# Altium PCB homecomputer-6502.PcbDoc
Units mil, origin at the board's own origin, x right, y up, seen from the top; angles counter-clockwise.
Board outline 6299.21 x 3937.01 mil, 2 copper layers (Top, Bottom), stack 61.811 mil thick; 48 components, 83 nets, 386 pads, 147 vias.
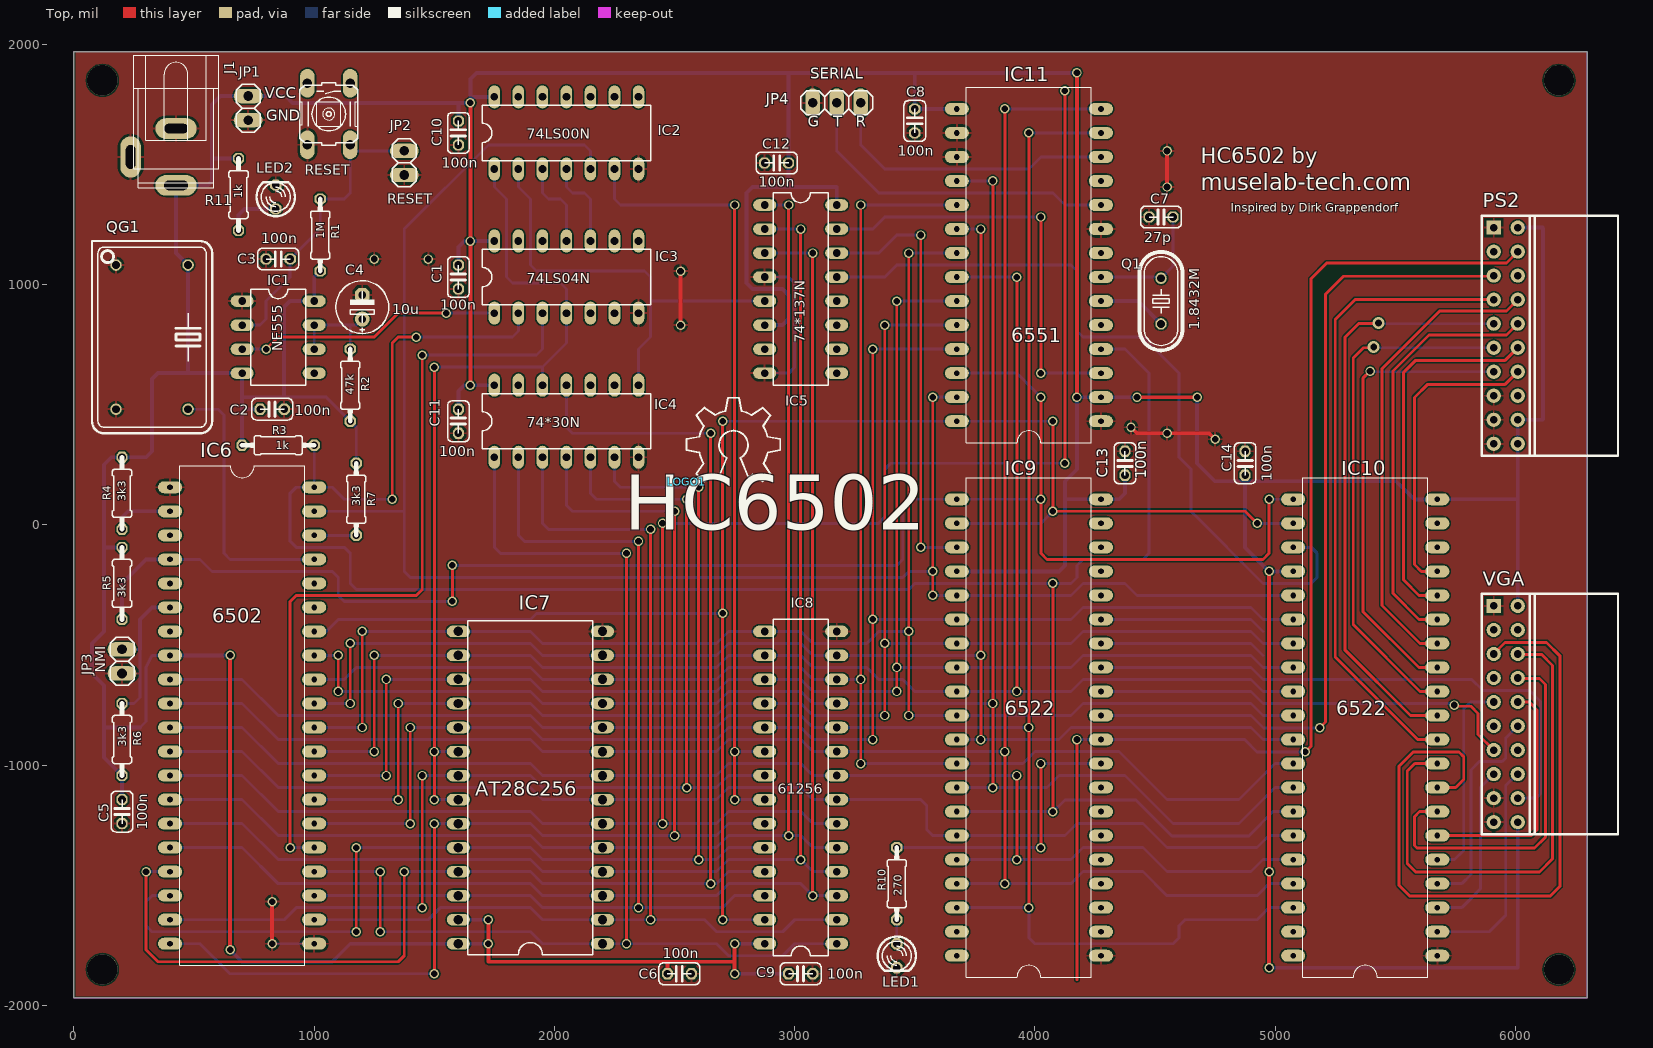
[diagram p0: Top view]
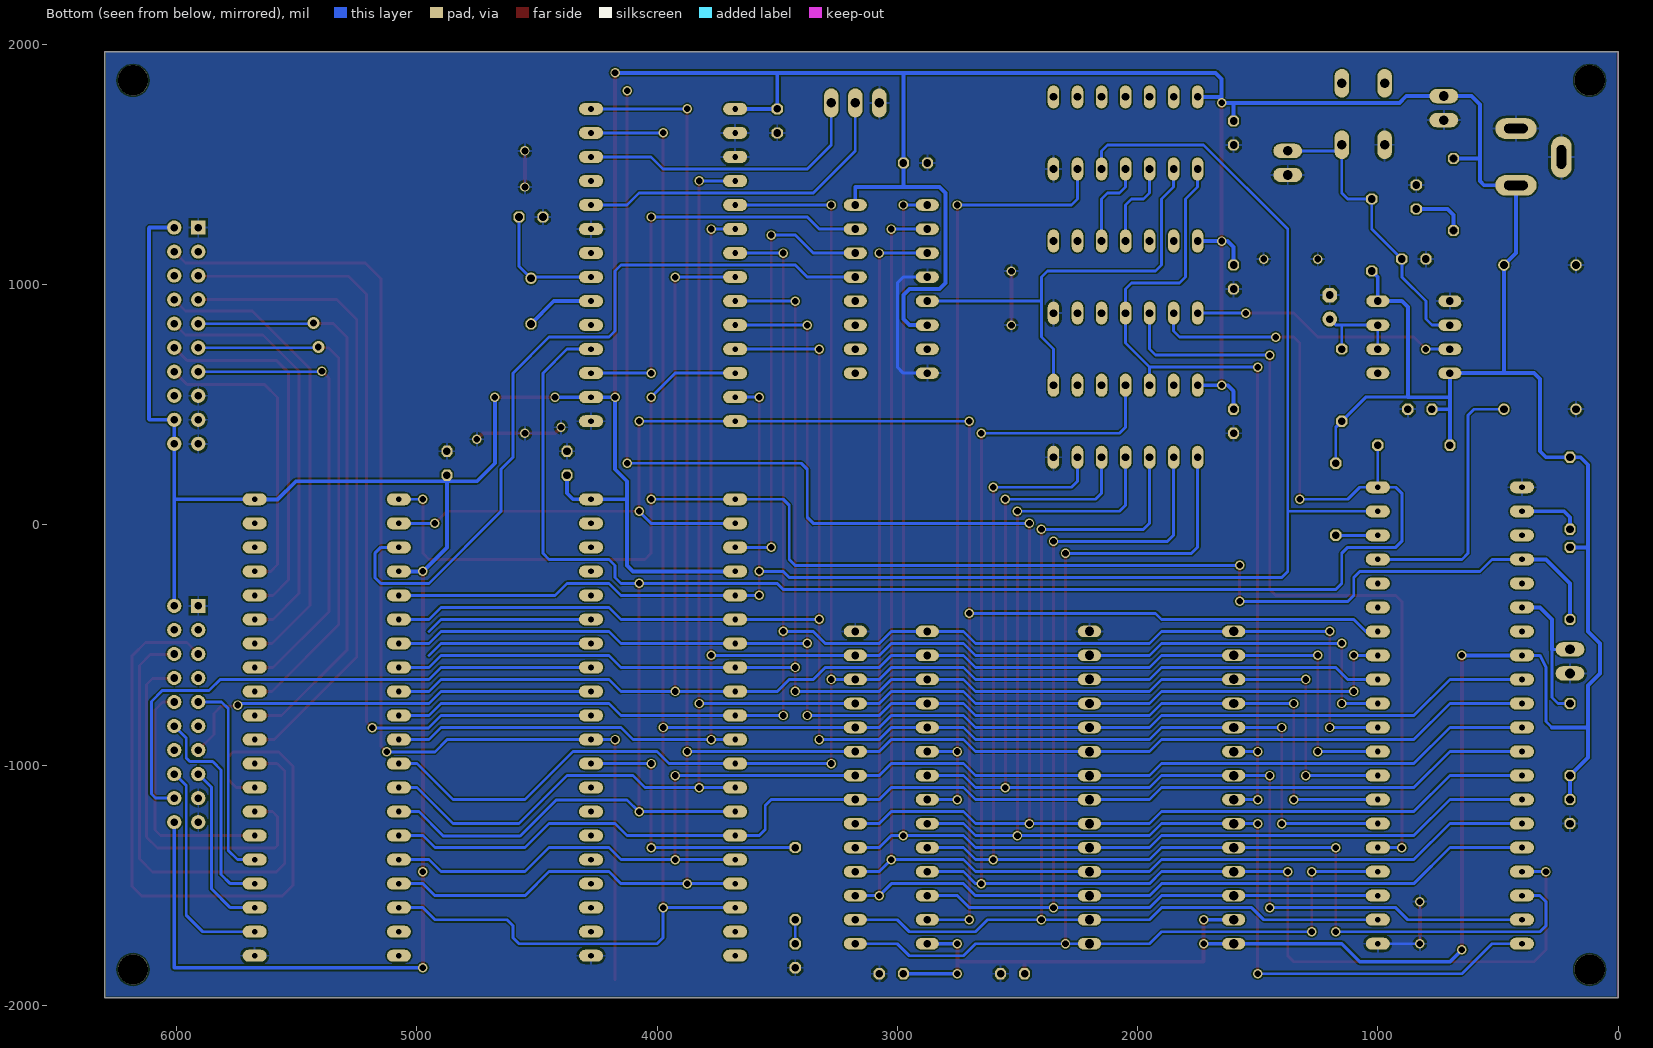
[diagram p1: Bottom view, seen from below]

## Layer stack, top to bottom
Top Solder: solder mask 0.4, Solder Resist, Dk 3.5
Top: signal copper 1.378
Dielectric 1: core 59.0551, FR-4, Dk 4.8
Bottom: signal copper 1.378
Bottom Solder: solder mask 0.4, Solder Resist, Dk 3.5

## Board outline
0,-1968.51 6299.21,-1968.51 6299.21,1968.51 0,1968.51

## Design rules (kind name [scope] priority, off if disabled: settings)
Clearance [All] p1: gap=5.91 ignorepadtopadclearanceinfootprint=FALSE except(0: SMDPad-SMDPad SMDPad-THPad SMDPad-Via)
Clearance "Clearance (Same Net)" [All] p2: gap=0 ignorepadtopadclearanceinfootprint=FALSE except(5.91: SMDPad-SMDPad SMDPad-THPad SMDPad-Via)
HoleSize HoleSize_1 [All] p1: absolutevalues=TRUE maxlimit=100000 minlimit=11.81 maxpercent=80.000 minpercent=20.000
HoleSize [All] p2: absolutevalues=TRUE maxlimit=100 minlimit=1 maxpercent=80.000 minpercent=20.000
HoleToHoleClearance mdViaViaSameLayer [All] p1: gap=19.68 allowstackedmicrovias=TRUE
HoleToHoleClearance [All] p2: gap=10 allowstackedmicrovias=TRUE
PasteMaskExpansion mlMinCreamFrame [All] p1: expansion=0
PasteMaskExpansion [All] p2: expansion=0
PolygonConnect PolygonConnect_1 [All] p1: connectstyle=Relief reliefconductorwidth=10 reliefentries=4 polygonreliefangle="90 Angle" airgapwidth=10
PolygonConnect [All] p2: connectstyle=Relief reliefconductorwidth=10 reliefentries=4 polygonreliefangle="90 Angle" airgapwidth=10
RoutingVias [All] p1: holewidth=28 width=50 viastyle="Through Hole" minholewidth=28 minwidth=50 maxholewidth=28 maxwidth=50
SilkToSilkClearance [All] p1 off: silktosilkclearance=10
SilkToSolderMaskClearance [IsPad] p1 off: minsilkscreentomaskgap=10 clearancetoexposedcopper=TRUE
SolderMaskExpansion mlMinStopFrame [All] p1: expansion=2.95
SolderMaskExpansion [All] p2: expansion=4
Width Width_1 [All] p1: maxlimit=100000 minlimit=5.91 preferedwidth=10
Width [All] p2: maxlimit=10 minlimit=10 preferedwidth=10
25 further rules are at their usual default settings.

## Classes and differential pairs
component class homecomputer-6502_5: J2 muselab-tech.com PS2 VGA
component class homecomputer-6502_0: C1 C2 C3 C4 C5 C8 C9 C10 C11 C12 C13 C14 IC1 IC3 J1 JP1 JP2 LED2 LOGO1 QG1 R1 R2 R3 R11 RESET
component class homecomputer-6502_1: IC2 IC4 IC5
component class homecomputer-6502_2: C6 IC6 IC7 IC8 JP3 R4 R5 R6 R7
component class homecomputer-6502_3: IC9 IC10 LED1 R10
component class homecomputer-6502_4: C7 IC11 JP4 Q1
net class A[0..15]: A0 A1 A2 A3 A4 A5 A6 A7 A8 A9 A10 A11 A12 A13 A14 A15
net class D[0..7]: D0 D1 D2 D3 D4 D5 D6 D7

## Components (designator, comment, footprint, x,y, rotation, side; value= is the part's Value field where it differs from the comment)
C1 "100n" C025-024X044 1600,1031.49 r90 top
C2 "100n" C025-024X044 825,481.49 r180 top
C3 "100n" C025-024X044 850,1106.49 r0 top
C4 "10u" E2,5-6E 1200,906.49 r90 top
C5 "100n" C025-024X044 200,-1193.51 r90 top
C6 "100n" C025-024X044 2520,-1868.51 r180 top
C7 "27p" C025-024X044 4525,1281.49 r0 top
C8 "100n" C025-024X044 3500,1681.49 r90 top
C9 "100n" C025-024X044 3025,-1868.51 r180 top
C10 "100n" C025-024X044 1600,1631.49 r90 top
C11 "100n" C025-024X044 1600,431.49 r90 top
C12 "100n" C025-024X044 2925,1506.49 r0 top
C13 "100n" C025-024X044 4375,256.49 r270 top
C14 "100n" C025-024X044 4875,256.49 r270 top
IC1 "NE555" DIL-08 850,781.49 r270 top
IC2 "74LS00N" DIL14 2050,1631.49 r0 top
IC3 "74LS04N" DIL14 2050,1031.49 r0 top
IC4 "74*30N" DIL14 2050,431.49 r0 top
IC5 "74*137N" DIL16 3025,981.49 r270 top
IC6 "6502" DIP40 700,-793.51 r270 top
IC7 "AT28C256" DIL28-6 1900,-1093.51 r90 top
IC8 "61256" DIL28-3 3025,-1093.51 r90 top
IC9 "6522" DIP40 3975,-843.51 r90 top
IC10 "6522" DIP40 5375,-843.51 r90 top locked
IC11 "6551" DIP28 3975,1081.49 r90 top
J1 "POWER1" SPC4078 425,1531.49 r270 top
JP1 "POWER2" 1X02 725,1735 r270 top
JP2 "RESET" 1X02 1375,1506.49 r270 top
JP3 "NMI" 1X02 200,-568.51 r270 top
JP4 "SERIAL" 1X03 3175,1756.49 r0 top
LED1 "LED3MM" LED3MM 3425,-1793.51 r270 top
LED2 "LED3MM" LED3MM 840,1365 r90 top
LOGO1 "OSHW_LOGO_8MILX0350-NT" OSHW_8X350_NOTEXT 2550,180 r0 top
muselab-tech.com "LOGO_MuseLab" LOGO_MUSELAB 5385,1495 r0 top
PS2 "IDC20" IDC20 5960,787.4 r270 top locked
Q1 "1.8432M" HC49U-V 4525,931.49 r90 top
QG1 "XO-14" DIL14S 325,781.49 r270 top
R1 "1M" 0204/7 1025,1206.49 r270 top
R2 "47k" 0204/7 1150,581.49 r270 top
R3 "1k" 0204/7 850,331.49 r180 top
R4 "3k3" 0204/7 200,131.49 r90 top
R5 "3k3" 0204/7 200,-243.51 r90 top
R6 "3k3" 0204/7 200,-893.51 r270 top
R7 "3k3" 0204/7 1175,106.49 r90 top
R10 "270" 0204/7 3425,-1493.51 r90 top
R11 "1k" 0204/7 685,1375 r90 top
RESET "10-XX" B3F-10XX 1060.63,1710.23 r270 top
VGA "IDC20" IDC20 5960,-787.4 r270 top locked

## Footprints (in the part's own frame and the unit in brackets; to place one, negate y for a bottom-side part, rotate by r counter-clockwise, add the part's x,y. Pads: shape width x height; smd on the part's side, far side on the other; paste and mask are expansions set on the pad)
1X02 [mil] "1X02"
  oval 60x120 hole 40: 1(-50,0) 2(50,0)
  silkscreen extent -100,-50 100,50
1X03 [mil] "1X03"
  oval 60x120 hole 40: 1(-100,0) 2(0,0) 3(100,0)
  silkscreen extent -150,-50 150,50
0204/7 [mil] "0204/7"
  oct 46.48x46.48 hole 32: 1(-150,0) 2(150,0)
  silkscreen extent -150,-40 150,40
B3F-10XX [mil] "B3F-10XX"
  oval 120x60 hole 40: 1(-128,89) 2(128,89) 3(-128,-89) 4(128,-89)
  silkscreen extent -130,-120 130,120
C025-024X044 [mil] "C025-024X044"
  oct 46.48x46.48 hole 32: 1(-50,0) 2(50,0)
  silkscreen extent -85,-45 85,45
DIL14 [mil] "DIL14"
  oval 48x96 hole 32: 1(-300,-150) 2(-200,-150) 3(-100,-150) 4(0,-150) 5(100,-150) 6(200,-150) 7(300,-150) 8(300,150) 9(200,150) 10(100,150) 11(0,150) 12(-100,150) 13(-200,150) 14(-300,150)
  silkscreen extent -350,-115 350,115
DIL14S [mil] "DIL14S"
  round 48 hole 32: 1(-300,-150) 7(300,-150) 8(300,150) 14(-300,150)
  silkscreen extent -400,-250 400,250
DIL16 [mil] "DIL16"
  oval 48x96 hole 32: 1(-350,-150) 2(-250,-150) 3(-150,-150) 4(-50,-150) 5(50,-150) 6(150,-150) 7(250,-150) 8(350,-150) 9(350,150) 10(250,150) 11(150,150) 12(50,150) 13(-50,150) 14(-150,150) 15(-250,150) 16(-350,150)
  silkscreen extent -400,-115 400,115
DIL28-3 [mil] "DIL28-3"
  oval 48x96 hole 32: 1(-650,-150) 2(-550,-150) 3(-450,-150) 4(-350,-150) 5(-250,-150) 6(-150,-150) 7(-50,-150) 8(50,-150) 9(150,-150) 10(250,-150) 11(350,-150) 12(450,-150) 13(550,-150) 14(650,-150) 15(650,150) 16(550,150) 17(450,150) 18(350,150) 19(250,150) 20(150,150) 21(50,150) 22(-50,150) 23(-150,150) 24(-250,150) 25(-350,150) 26(-450,150) 27(-550,150) 28(-650,150)
  silkscreen extent -700,-115 700,115
DIL28-6 [mil] "DIL28-6"
  oval 48x96 hole 39.37: 1(-650,-300) 2(-550,-300) 3(-450,-300) 4(-350,-300) 5(-250,-300) 6(-150,-300) 7(-50,-300) 8(50,-300) 9(150,-300) 10(250,-300) 11(350,-300) 12(450,-300) 13(550,-300) 14(650,-300) 15(650,300) 16(550,300) 17(450,300) 18(350,300) 19(250,300) 20(150,300) 21(50,300) 22(-50,300) 23(-150,300) 24(-250,300) 25(-350,300) 26(-450,300) 27(-550,300) 28(-650,300)
  silkscreen extent -695,-260 695,260
DIL-08 [mil] "DIL-08"
  oval 48x96 hole 32: 1(-150,-150) 2(-50,-150) 3(50,-150) 4(150,-150) 5(150,150) 6(50,150) 7(-50,150) 8(-150,150)
  silkscreen extent -200,-115 200,115
DIP28 [mil] "DIP28"
  oval 50x100 hole 24: 1(-650,-300) 2(-550,-300) 3(-450,-300) 4(-350,-300) 5(-250,-300) 6(-150,-300) 7(-50,-300) 8(50,-300) 9(150,-300) 10(250,-300) 11(350,-300) 12(450,-300) 13(550,-300) 14(650,-300) 15(650,300) 16(550,300) 17(450,300) 18(350,300) 19(250,300) 20(150,300) 21(50,300) 22(-50,300) 23(-150,300) 24(-250,300) 25(-350,300) 26(-450,300) 27(-550,300) 28(-650,300)
  silkscreen extent -740,-260 740,260
DIP40 [mil] "DIP40"
  oval 50x100 hole 24: 1(-950,-300) 2(-850,-300) 3(-750,-300) 4(-650,-300) 5(-550,-300) 6(-450,-300) 7(-350,-300) 8(-250,-300) 9(-150,-300) 10(-50,-300) 11(50,-300) 12(150,-300) 13(250,-300) 14(350,-300) 15(450,-300) 16(550,-300) 17(650,-300) 18(750,-300) 19(850,-300) 20(950,-300) 21(950,300) 22(850,300) 23(750,300) 24(650,300) 25(550,300) 26(450,300) 27(350,300) 28(250,300) 29(150,300) 30(50,300) 31(-50,300) 32(-150,300) 33(-250,300) 34(-350,300) 35(-450,300) 36(-550,300) 37(-650,300) 38(-750,300) 39(-850,300) 40(-950,300)
  silkscreen extent -1040,-260 1040,260
E2,5-6E [mil] "E2,5-6E"
  round 62 hole 32: +(-50,0)
  oct 60.03x60.03 hole 32: -(50,0)
  silkscreen extent -110,-110 110,110
HC49U-V [mil] "HC49U-V"
  round 48 hole 32: 1(-95,0) 2(95,0)
  silkscreen extent -205,-90 205,90
IDC20 [mm]
  rect 1.5x1.5 hole 0.8: 1(-11.43,-1.27)
  round 1.5 hole 0.8: 2(-11.43,1.27) 3(-8.89,-1.27) 4(-8.89,1.27) 5(-6.35,-1.27) 6(-6.35,1.27) 7(-3.81,-1.27) 8(-3.81,1.27) 9(-1.27,-1.27) 10(-1.27,1.27) 11(1.27,-1.27) 12(1.27,1.27) 13(3.81,-1.27) 14(3.81,1.27) 15(6.35,-1.27) 16(6.35,1.27) 17(8.89,-1.27) 18(8.89,1.27) 19(11.43,-1.27) 20(11.43,1.27)
  silkscreen extent -12.7,-2.54 12.7,11.87
LED3MM [mil] "LED3MM"
  oct 46.48x46.48 hole 32: A(-50,0) K(50,0)
  silkscreen extent -80,-80 62,80
LOGO_MUSELAB [mil]
OSHW_8X350_NOTEXT [mil] "OSHW_8X350_NOTEXT"
  silkscreen extent 0,0 391,350
SPC4078 [mil] "SPC4078"
  oval 86x172 hole 39.37 slot 98.43 at 90 deg: 1(-118.11,0) 3(118.11,0)
  oval 172x86 hole 39.37 slot 98.43 at 0 deg: 2(0,-188.98)
  silkscreen extent -423,-177 128,177

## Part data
C1 C2 C3 C5 C6 C7 C8 C9 C10 C11 C12 C13 C14: library part C-EU025-024X044, "CAPACITOR, European symbol"
C4: library part CPOL-EUE2,5-6E, "POLARIZED CAPACITOR, European symbol"
IC1: "General purpose bipolar Timer", MPN=NE555N
IC2: library part 74*00N, "Quad 2-input NAND gate"
IC3: library part 74*04N, "Hex INVERTER"
IC4: "8-input NAND gate"
IC5: "3-line to 8-line DECODER/DEMULTIPLEXER, address LATCH"
IC6: "6502 processor"
IC7: "EEPROM 32Kx8 256k bit   The AT28C256 is a high-performance Electrically Erasable and Programmable Read Only Memory. Its 256K of memory is organized as 32,768 words by 8 bits."
IC8: "MEMORY"
IC9 IC10: "I/O device: two 8-bits ports, handshake lines, timers."
IC11: "ACIA. Capable of RS-232"
J1: library part JACK-PLUG1, "DC POWER JACK Power Jack, DC, Right Angle, Through Hole, Rated 5A at 16VDC, PC Terminals   Distributor: Farnell (www.Farnell.de) Drawing: 84N1161.pdf / 84N1162.pdf Manufacturer: SPC Technology (www.spctechnology.com) Type: SPC4077 / SPC 4078"
JP1 JP2 JP3: library part PINHD-1X2_2.54, "PIN HEADER"
JP4: library part PINHD-1X3_2.54, "PIN HEADER"
LED1 LED2: "LED   OSRAM: - CHIPLED LG R971, LG N971, LY N971, LG Q971, LY Q971, LO R971, LY R971 LH N974, LH R974 LS Q976, LO Q976, LY Q976 LO Q996 - Hyper CHIPLED LW Q18S LB Q993, LB Q99A, LB R99A - SideLED LS A670, LO A670, LY A670, LG A670, LP A670 LB A673, LV A673, LT A673, LW A673 LH A674 LY A675 LS A676, LA A676, LO A676, LY A676, LW A676 LS A679, LY A679, LG A679 -  Hyper Micro SIDELED® LS Y876, LA Y876, LO Y876, LY Y876 LT Y87S - SmartLED LW L88C, LW L88S LB L89C, LB L89S, LG L890 LS L89K, LO L89K, LY L89K LS L896, LA L896, LO L896, LY L896 - TOPLED LS T670, LO T670, LY T670, LG T670, LP T670 LSG T670, LSP T670, LSY T670, LOP T670, LYG T670 LG T671, LOG T671, LSG T671 LB T673, LV T673, LT T673, LW T673 LH T674 LS T676, LA T676, LO T676, LY T676, LB T676, LH T676, LSB T676, LW T676 LB T67C, LV T67C, LT T67C, LS T67K, LO T67K, LY T67K, LW E67C LS E67B, LA E67B, LO E67B, LY E67B, LB E67C, LV E67C, LT E67C LW T67C LS T679, LY T679, LG T679 LS T770, LO T770, LY T770, LG T770, LP T770 LB T773, LV T773, LT T773, LW T773 LH T774 LS E675, LA E675, LY E675, LS T675 LS T776, LA T776, LO T776, LY T776, LB T776 LHGB T686 LT T68C, LB T68C - Hyper Mini TOPLED® LB M676 - Mini TOPLED Santana® LG M470 LS M47K, LO M47K, LY M47K    Source: http://www.osram.convergy.de   LUXEON: - LUMILED® LXK2-PW12-R00, LXK2-PW12-S00, LXK2-PW14-U00, LXK2-PW14-V00 LXK2-PM12-R00, LXK2-PM12-S00, LXK2-PM14-U00 LXK2-PE12-Q00, LXK2-PE12-R00, LXK2-PE12-S00, LXK2-PE14-T00, LXK2-PE14-U00 LXK2-PB12-K00, LXK2-PB12-L00, LXK2-PB12-M00, LXK2-PB14-N00, LXK2-PB14-P00, LXK2-PB14-Q00 LXK2-PR12-L00, LXK2-PR12-M00, LXK2-PR14-Q00, LXK2-PR14-R00 LXK2-PD12-Q00, LXK2-PD12-R00, LXK2-PD12-S00 LXK2-PH12-R00, LXK2-PH12-S00 LXK2-PL12-P00, LXK2-PL12-Q00, LXK2-PL12-R00    Source: www.luxeon.com   KINGBRIGHT:   KA-3528ASYC Source: www.kingbright.com"
Q1: library part CRYSTALHC49U-V, "CRYSTAL"
QG1: "CRYSTAL"
R1 R2 R3 R4 R5 R6 R7 R10 R11: library part R-EU_0204/7, "RESISTOR, European symbol"
RESET: "OMRON SWITCH", MPN=B3F-1000

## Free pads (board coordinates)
  round 125.98 hole 125.98: 1(118.11,-1850.4) 1(118.11,1850.39) 1(6181.1,-1850.4) 1(6181.1,1850.39)

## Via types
v1: diameter 39.37/39.37 (per signal layer), hole 27.56, Top to Bottom, 145 vias
v2: diameter 50, hole 28, Top to Bottom, 2 vias

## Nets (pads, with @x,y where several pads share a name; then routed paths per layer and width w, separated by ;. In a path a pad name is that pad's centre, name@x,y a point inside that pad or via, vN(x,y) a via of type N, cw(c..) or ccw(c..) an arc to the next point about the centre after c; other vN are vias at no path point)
A0: IC6.9 IC7.10 IC8.10 IC9.38 IC10.38 IC11.13 | length 8851
  Top w12: v1(3975,-1593.51) v1(3975,-843.51) v1(3975,1631.49)
  Bottom w12: IC6.9 700,-643.51 850,-793.51 1900,-793.51 1950,-843.51 IC7.10 2675,-843.51 2725,-793.51 3025,-793.51 3075,-843.51 IC8.10 v1(3975,-843.51) ; IC9.38 v1(3975,-1593.51) 3975,-1718.51 4000,-1743.51 4575,-1743.51 4600,-1718.51 4600,-1668.51 4625,-1643.51 4925,-1643.51 4975,-1593.51 IC10.38 ; v1(3975,1631.49) IC11.13
A1: IC6.10 IC7.9 IC8.9 IC9.37 IC10.37 IC11.14 | length 8707.1
  Top w12: v1(3875,-1493.51) v1(3875,-943.51) v1(3875,1731.49)
  Bottom w12: IC6.10 700,-743.51 850,-893.51 1900,-893.51 1950,-943.51 IC7.9 2675,-943.51 2725,-893.51 3025,-893.51 3075,-943.51 IC8.9 v1(3875,-943.51) ; IC9.37 v1(3875,-1493.51) 4150,-1493.51 4200,-1443.51 4450,-1443.51 4550,-1543.51 4925,-1543.51 4975,-1493.51 IC10.37 ; v1(3875,1731.49) IC11.14
A2: IC6.11 IC7.8 IC8.8 IC9.36 IC10.36 | length 5482.1
  Top w12: v1(3925,-1393.51) v1(3925,-1043.51)
  Bottom w12: IC6.11 700,-843.51 850,-993.51 1900,-993.51 1950,-1043.51 IC7.8 2675,-1043.51 2725,-993.51 3025,-993.51 3075,-1043.51 IC8.8 v1(3925,-1043.51) ; IC9.36 v1(3925,-1393.51) 4150,-1393.51 4200,-1343.51 4450,-1343.51 4550,-1443.51 4900,-1443.51 4950,-1393.51 IC10.36
A3: IC6.12 IC7.7 IC8.7 IC9.35 IC10.35 | length 5002.8
  Bottom w12: IC6.12 700,-943.51 850,-1093.51 1900,-1093.51 1950,-1143.51 IC7.7 2675,-1143.51 2725,-1093.51 3025,-1093.51 3075,-1143.51 IC8.7 3525,-1143.51 3550,-1168.51 3550,-1268.51 3575,-1293.51 IC9.35 4125,-1293.51 4175,-1243.51 4450,-1243.51 4550,-1343.51 4925,-1343.51 4975,-1293.51 IC10.35
A4: IC6.13 IC7.6 IC8.6 | length 7595
  Top w12: v1(2450,-1243.51) v1(2450,6.49) ; v1(4125,256.49) v1(4125,1806.49)
  Bottom w12: IC6.13 700,-1043.51 850,-1193.51 1900,-1193.51 1950,-1243.51 IC7.6 v1(2450,-1243.51) 2675,-1243.51 2725,-1193.51 3025,-1193.51 3075,-1243.51 IC8.6 ; v1(2450,6.49) 3350,6.49 3375,31.49 3375,231.49 3400,256.49 v1(4125,256.49)
A5: IC5.1 IC6.14 IC7.5 IC8.5 | length 5624.3
  Top w12: v1(2975,-1293.51) v1(2975,1331.49)
  Bottom w12: IC6.14 700,-1143.51 850,-1293.51 1900,-1293.51 1950,-1343.51 IC7.5 2675,-1343.51 2725,-1293.51 v1(2975,-1293.51) 3025,-1293.51 3075,-1343.51 IC8.5 ; IC5.1 v1(2975,1331.49)
A6: IC5.2 IC6.15 IC7.4 IC8.4 | length 5674.3
  Top w12: v1(3025,-1393.51) v1(3025,1231.49)
  Bottom w12: IC6.15 700,-1243.51 850,-1393.51 1900,-1393.51 1950,-1443.51 IC7.4 2675,-1443.51 2725,-1393.51 v1(3025,-1393.51) 3075,-1443.51 IC8.4 ; IC5.2 v1(3025,1231.49)
A7: IC5.3 IC6.16 IC7.3 IC8.3 | length 5774.3
  Top w12: v1(3075,-1543.51) v1(3075,1131.49)
  Bottom w12: IC6.16 700,-1343.51 850,-1493.51 1900,-1493.51 1950,-1543.51 IC7.3 2450,-1543.51 2675,-1543.51 2725,-1493.51 3025,-1493.51 v1(3075,-1543.51) IC8.3 ; IC5.3 v1(3075,1131.49)
A8: IC4.11 IC6.17 IC7.25 IC8.25 | length 6307.8
  Top w12: v1(300,-1443.51) 300,-1768.51 350,-1818.51 1350,-1818.51 1375,-1793.51 v1(1375,-1443.51) ; v1(2650,-1493.51) v1(2650,381.49)
  Bottom w12: v1(300,-1443.51) IC6.17 ; IC7.25 v1(1375,-1443.51) 1900,-1443.51 1950,-1493.51 v1(2650,-1493.51) 2675,-1493.51 2725,-1443.51 IC8.25 ; IC4.11 2050,406.49 2075,381.49 v1(2650,381.49)
A9: IC4.6 IC6.18 IC7.24 IC8.24 | length 5197.5
  Top w12: v1(1175,-1693.51) v1(1175,-1343.51) ; v1(2600,-1393.51) v1(2600,156.49)
  Bottom w12: IC6.18 325,-1543.51 300,-1568.51 300,-1668.51 325,-1693.51 v1(1175,-1693.51) ; v1(1175,-1343.51) IC7.24 1900,-1343.51 1950,-1393.51 v1(2600,-1393.51) 2675,-1393.51 2725,-1343.51 IC8.24 ; IC4.6 2250,181.49 2275,156.49 v1(2600,156.49)
A10: IC4.5 IC6.19 IC7.21 IC8.21 | length 4847.5
  Top w12: v1(1450,-1593.51) v1(1450,-1043.51) ; v1(2550,-1093.51) v1(2550,106.49)
  Bottom w12: IC6.19 875,-1643.51 925,-1593.51 v1(1450,-1593.51) ; v1(1450,-1043.51) IC7.21 1900,-1043.51 1950,-1093.51 v1(2550,-1093.51) 2675,-1093.51 2725,-1043.51 IC8.21 ; IC4.5 2150,131.49 2175,106.49 v1(2550,106.49)
A11: IC4.4 IC6.20 IC7.23 IC8.23 | length 5203.6
  Top w12: v1(1500,-1868.51) v1(1500,-1243.51) ; v1(2500,-1293.51) v1(2500,56.49)
  Bottom w12: IC6.20 525,-1743.51 650,-1868.51 v1(1500,-1868.51) ; v1(1500,-1243.51) IC7.23 1900,-1243.51 1950,-1293.51 v1(2500,-1293.51) 2675,-1293.51 2725,-1243.51 IC8.23 ; IC4.4 2050,81.49 2075,56.49 v1(2500,56.49)
A12: IC4.3 IC6.22 IC7.2 IC8.2 | length 4618.2
  Top w12: v1(2400,-1643.51) v1(2400,-18.51)
  Bottom w12: IC6.22 1475,-1643.51 1525,-1593.51 1900,-1593.51 1950,-1643.51 IC7.2 v1(2400,-1643.51) 2625,-1643.51 2675,-1693.51 2950,-1693.51 3000,-1643.51 IC8.2 ; IC4.3 1950,6.49 1975,-18.51 v1(2400,-18.51)
A13: IC4.2 IC6.23 IC7.26 IC8.26 | length 4276.8
  Top w12: v1(2350,-1593.51) v1(2350,-68.51)
  Bottom w12: IC6.23 IC7.26 1900,-1543.51 1950,-1593.51 v1(2350,-1593.51) 2700,-1593.51 2750,-1543.51 IC8.26 ; IC4.2 1850,-43.51 1875,-68.51 v1(2350,-68.51)
A14: IC4.1 IC6.24 IC7.1 IC8.1 | length 5047.5
  Top w12: v1(1275,-1693.51) v1(1275,-1443.51) ; v1(2300,-1743.51) v1(2300,-118.51)
  Bottom w12: IC6.24 v1(1275,-1443.51) ; v1(1275,-1693.51) 1900,-1693.51 1950,-1743.51 IC7.1 v1(2300,-1743.51) 2675,-1743.51 2725,-1793.51 2950,-1793.51 3000,-1743.51 IC8.1 ; IC4.1 1750,-93.51 1775,-118.51 v1(2300,-118.51)
A15: IC3.3 IC6.25 | length 3331.1
  Top w12: v1(900,-1343.51) 900,-318.51 925,-293.51 1425,-293.51 1450,-268.51 v1(1450,706.49)
  Bottom w12: v1(900,-1343.51) IC6.25 ; v1(1450,706.49) 1925,706.49 1950,731.49 IC3.3
D0: IC6.33 IC7.11 IC8.11 IC9.33 IC10.33 IC11.18 | length 7277.8
  Top w12: v1(1100,-693.51) v1(1100,-543.51) ; v1(3825,-1093.51) v1(3825,-743.51) v1(3825,1431.49)
  Bottom w12: IC6.33 v1(1100,-543.51) ; v1(1100,-693.51) 1900,-693.51 1950,-743.51 IC7.11 2675,-743.51 2725,-693.51 3025,-693.51 3075,-743.51 IC8.11 v1(3825,-743.51) ; IC9.33 v1(3825,-1093.51) 4050,-1093.51 4100,-1043.51 4375,-1043.51 4575,-1243.51 4850,-1243.51 5000,-1093.51 IC10.33 ; IC11.18 v1(3825,1431.49)
D1: IC6.32 IC7.12 IC8.12 IC9.32 IC10.32 IC11.19 | length 7048.5
  Top w12: v1(3275,-993.51) v1(3275,-643.51) v1(3275,1331.49)
  Bottom w12: IC6.32 1125,-643.51 1175,-593.51 1900,-593.51 1950,-643.51 IC7.12 2675,-643.51 2725,-593.51 3025,-593.51 3075,-643.51 IC8.12 v1(3275,-643.51) ; v1(3275,-993.51) IC9.32 3950,-993.51 4000,-943.51 4350,-943.51 4550,-1143.51 4850,-1143.51 5000,-993.51 IC10.32 ; v1(3275,1331.49) IC11.19
D2: IC6.31 IC7.13 IC8.13 IC9.31 IC10.31 IC11.20 | length 6753.6
  Top w12: v1(1150,-743.51) v1(1150,-493.51) ; v1(3775,-893.51) v1(3775,-543.51) v1(3775,1231.49)
  Bottom w12: IC6.31 v1(1150,-743.51) ; v1(1150,-493.51) 1900,-493.51 1950,-543.51 IC7.13 2675,-543.51 2725,-493.51 3025,-493.51 3075,-543.51 IC8.13 v1(3775,-543.51) ; IC9.31 v1(3775,-893.51) 4100,-893.51 4150,-843.51 4900,-843.51 4950,-893.51 IC10.31 ; IC11.20 v1(3775,1231.49)
D3: IC6.30 IC7.15 IC8.15 IC9.30 IC10.30 IC11.21 | length 6724.3
  Top w12: v1(1200,-843.51) v1(1200,-443.51) ; v1(3475,-793.51) v1(3475,-443.51) v1(3475,1131.49)
  Bottom w12: IC6.30 v1(1200,-843.51) ; v1(1200,-443.51) IC7.15 1900,-443.51 1950,-493.51 2675,-493.51 2725,-443.51 IC8.15 3025,-443.51 3075,-493.51 3300,-493.51 3350,-443.51 v1(3475,-443.51) ; v1(3475,-793.51) IC9.30 4150,-793.51 4200,-743.51 4900,-743.51 4950,-793.51 IC10.30 ; v1(3475,1131.49) IC11.21
D4: IC6.29 IC7.16 IC8.16 IC9.29 IC10.29 IC11.22 | length 6595
  Top w12: v1(1250,-943.51) v1(1250,-543.51) ; v1(3925,-693.51) v1(3925,1031.49)
  Bottom w12: IC6.29 v1(1250,-943.51) ; v1(1250,-543.51) IC7.16 1900,-543.51 1950,-593.51 2675,-593.51 2725,-543.51 IC8.16 3025,-543.51 3075,-593.51 3300,-593.51 3350,-643.51 3450,-643.51 3500,-693.51 IC9.29 v1(3925,-693.51) 4150,-693.51 4200,-643.51 4900,-643.51 4950,-693.51 IC10.29 ; IC11.22 v1(3925,1031.49)
D5: IC6.28 IC7.17 IC8.17 IC9.28 IC10.28 IC11.23 | length 6453.6
  Top w12: v1(1300,-1043.51) v1(1300,-643.51) ; v1(3425,-693.51) v1(3425,-593.51) v1(3425,931.49)
  Bottom w12: IC6.28 v1(1300,-1043.51) ; v1(1300,-643.51) IC7.17 1900,-643.51 1950,-693.51 2675,-693.51 2725,-643.51 IC8.17 3025,-643.51 3075,-693.51 v1(3425,-693.51) ; v1(3425,-593.51) IC9.28 4150,-593.51 4200,-543.51 4900,-543.51 4950,-593.51 IC10.28 ; v1(3425,931.49) IC11.23
D6: IC6.27 IC7.18 IC8.18 IC9.27 IC10.27 IC11.24 | length 6503.6
  Top w12: v1(1350,-1143.51) v1(1350,-743.51) ; v1(3375,-793.51) v1(3375,-493.51) v1(3375,831.49)
  Bottom w12: IC6.27 v1(1350,-1143.51) ; v1(1350,-743.51) IC7.18 1900,-743.51 1950,-793.51 2675,-793.51 2725,-743.51 IC8.18 3025,-743.51 3075,-793.51 v1(3375,-793.51) ; v1(3375,-493.51) IC9.27 4150,-493.51 4200,-443.51 4900,-443.51 4950,-493.51 IC10.27 ; v1(3375,831.49) IC11.24
D7: IC6.26 IC7.19 IC8.19 IC9.26 IC10.26 IC11.25 | length 6553.6
  Top w12: v1(1400,-1243.51) v1(1400,-843.51) ; v1(3325,-893.51) v1(3325,-393.51) v1(3325,731.49)
  Bottom w12: IC6.26 v1(1400,-1243.51) ; v1(1400,-843.51) IC7.19 1900,-843.51 1950,-893.51 2675,-893.51 2725,-843.51 IC8.19 3025,-843.51 3075,-893.51 v1(3325,-893.51) ; v1(3325,-393.51) IC9.26 4150,-393.51 4200,-343.51 4900,-343.51 4950,-393.51 IC10.26 ; v1(3325,731.49) IC11.25
GND: C1.1 C2.1 C3.1 C4.- C5.1 C6.1 C7.1 C8.1 C9.1 C10.1 C11.1 C12.1 C13.1 C14.1 IC1.1 IC2.7 IC3.7 IC4.7 IC5.4 IC5.8 IC6.1 IC6.21 IC7.14 IC8.14 IC9.1 IC10.1 IC11.1 IC11.9 IC11.16 IC11.17 J1.1 J1.2 JP1.2 JP2.2 JP3.2 JP4.1 LED1.K LED2.K PS2.1 PS2.15 PS2.17 PS2.19 QG1.1 QG1.7 RESET.4 VGA.1 VGA.17 VGA.19 | length 1716.4
  Top w16: v1(825,-1743.51) v1(825,-1568.51) ; v1(2525,831.49) v1(2525,1056.49) ; v1(4400,406.49) 4425,381.49 v1(4550,381.49) 4725,381.49 v1(4750,356.49) ; v1(4550,1406.49) v1(4550,1556.49)
  Bottom w12: v1(825,-1743.51) IC6.21 ; IC5.8 2975,631.49 3000,656.49 3000,1006.49 2975,1031.49 IC5.4
  other v1: 1250,1106.49 1475,1106.49
NetC3_2: C3.2 IC1.2 JP2.1 R1.1 RESET.2 | length 1265.2
  Bottom w12: IC1.2 775,831.49 800,856.49 800,931.49 900,1031.49 C3.2 1025,1231.49 R1.1 1125,1356.49 1150,1381.49 1150,1556.12 RESET.2@1149.63,1556.49 ; RESET.2 RESET.2@1149.63,1556.49 ; JP2.1 RESET.2@1149.63,1556.49
NetC4_+: C4.+ IC1.6 IC1.7 R2.1 | length 410.4
  Bottom w12: IC1.6 IC1.7 1150,831.49 ; R2.1 1150,831.49 ; C4.+ 1175,831.49 1150,831.49
NetC7_2: C7.2 IC11.7 Q1.2 | length 527.8
  Bottom w12: IC11.7 4520,1031.49 Q1.2 4575,1076.49 C7.2
NetIC1_3: IC1.3 IC3.1 | length 1112.1
  Top w12: v1(800,731.49) 850,781.49 1250,781.49 1350,881.49 v1(1550,881.49)
  Bottom w12: IC1.3 v1(800,731.49) ; v1(1550,881.49) IC3.1
NetIC2_1: IC2.1 IC3.4 IC4.12 IC7.20 IC7.22 | length 3757.8
  Top w12: v1(1500,-1143.51) v1(1500,-943.51) v1(1500,656.49)
  Bottom w12: v1(1500,-1143.51) IC7.22 ; v1(1500,-943.51) IC7.20 ; v1(1500,656.49) 1950,656.49 ; IC2.1 1750,1406.49 1800,1356.49 1800,1031.49 1825,1006.49 2025,1006.49 2050,981.49 2050,756.49 ; IC4.12 1950,656.49 ; IC3.4 2050,756.49 ; 1950,656.49 2050,756.49
NetIC2_2: IC2.2 IC4.8 IC5.5 | length 1887.1
  Bottom w12: IC2.2 1850,1406.49 1900,1356.49 1900,1081.49 1925,1056.49 2375,1056.49 2400,1031.49 2400,931.49 ; IC4.8 2350,731.49 2400,781.49 2400,931.49 ; IC5.5 2400,931.49
NetIC2_3: IC2.3 IC3.11 | length 370.7
  Bottom w12: IC2.3 1950,1381.49 1975,1356.49 2025,1356.49 2050,1331.49 IC3.11
NetIC2_4: IC2.4 IC3.10 | length 370.7
  Bottom w12: IC2.4 2050,1406.49 2075,1381.49 2125,1381.49 2150,1356.49 IC3.10
NetIC2_5: IC2.5 IC6.39 IC9.25 IC10.25 IC11.27 | length 7492.5
  Top w12: v1(3575,-293.51) v1(3575,-193.51) v1(3575,531.49)
  Bottom w12: IC6.39 1375,56.49 ; IC2.5 2150,1556.49 2125,1581.49 1725,1581.49 1375,1231.49 1375,56.49 ; v1(3575,-293.51) IC9.25 4150,-293.51 4200,-243.51 4375,-243.51 4425,-293.51 IC10.25 ; v1(3575,-193.51) 3475,-193.51 3450,-218.51 1400,-218.51 1375,-193.51 1375,56.49 ; v1(3575,531.49) IC11.27
NetIC2_6: IC2.6 IC8.20 IC8.22 | length 3360.4
  Top w12: v1(2750,-1143.51) v1(2750,-943.51) v1(2750,1331.49)
  Bottom w12: IC2.6 2250,1356.49 2275,1331.49 v1(2750,1331.49) ; v1(2750,-1143.51) IC8.22 ; v1(2750,-943.51) IC8.20
NetIC3_2: IC3.2 IC6.40 IC9.34 IC10.34 IC11.4 R3.1 | length 9389.9
  Top w12: v1(1325,106.49) 1325,756.49 1350,781.49 v1(1425,781.49) ; v1(4075,-1193.51) v1(4075,-243.51)
  Bottom w12: R3.1 IC6.40 ; v1(1325,106.49) 1125,106.49 1075,156.49 IC6.40 ; v1(1425,781.49) 1825,781.49 1850,806.49 IC3.2 ; IC9.34 v1(4075,-1193.51) 4076.49,-1193.51 4125,-1145 4420,-1145 4570,-1295 4890,-1295 4991.49,-1193.51 IC10.34 ; IC11.4 4375,731.49 4475,631.49 4475,-118.51 4450,-143.51 4200,-143.51 4175,-168.51 4175,-218.51 4150,-243.51 v1(4075,-243.51) 3500,-243.51 3475,-268.51 1175,-268.51 1150,-243.51 1150,-118.51 1125,-93.51 925,-93.51 900,-68.51 900,131.49 925,156.49 IC6.40
NetIC5_13: IC5.13 IC10.23 | length 3244.2
  Bottom w12: IC5.13 3375,1031.49 3425,1081.49 4150,1081.49 4175,1056.49 4175,806.49 4200,781.49 4450,781.49 4600,631.49 4600,281.49 4650,231.49 4650,56.49 4950,-243.51 5150,-243.51 5175,-218.51 5175,-118.51 5150,-93.51 IC10.23
NetIC5_14: IC5.14 IC9.23 | length 1831.1
  Top w12: v1(3525,-93.51) v1(3525,1206.49)
  Bottom w12: IC5.14 3350,1131.49 3425,1206.49 v1(3525,1206.49) ; v1(3525,-93.51) IC9.23
NetIC5_15: IC5.15 IC11.3 | length 1770.7
  Top w12: v1(4025,631.49) v1(4025,1281.49)
  Bottom w12: IC5.15 3325,1231.49 3375,1281.49 v1(4025,1281.49) ; v1(4025,631.49) IC11.3
NetIC6_2: IC6.2 R4.1 | length 260.4
  Bottom w16: R4.1 200,31.49 225,56.49 IC6.2
NetIC6_4: IC6.4 IC9.21 IC10.21 IC11.26 R5.1 | length 6865.7
  Top w12: v1(1575,-318.51) v1(1575,-168.51) ; v1(4025,531.49) 4025,481.49 v1(4025,106.49) 4025,-118.51 4050,-143.51 4950,-143.51 4975,-118.51 v1(4975,106.49)
  Bottom w12: IC6.4 525,-143.51 575,-193.51 1075,-193.51 1100,-218.51 1100,-293.51 1125,-318.51 v1(1575,-318.51) ; v1(1575,-168.51) 3425,-168.51 3450,-143.51 3450,81.49 3475,106.49 IC9.21 v1(4025,106.49) ; IC11.26 3925,631.49 v1(4025,531.49) ; v1(4975,106.49) IC10.21
  Bottom w16: R5.1 200,-243.51 300,-143.51 IC6.4
NetIC6_6: IC6.6 JP3.1 R6.1 | length 631.1
  Bottom w12: R6.1 250,-743.51 275,-718.51 275,-518.51 JP3.1
  Bottom w16: 275,-518.51 275,-393.51 325,-343.51 IC6.6
NetIC6_34: IC6.34 IC8.27 IC9.22 IC10.22 IC11.28 | length 7172.5
  Top w12: v1(2700,-1643.51) v1(2700,-368.51) v1(2700,431.49) ; v1(4075,431.49) v1(4075,56.49) 4425,56.49 4875,56.49 v1(4925,6.49)
  Bottom w12: IC6.34 1050,-443.51 1100,-393.51 1900,-393.51 1925,-368.51 v1(2700,-368.51) ; v1(2700,-1643.51) IC8.27 ; v1(2700,431.49) 3550,431.49 IC11.28 v1(4075,431.49) ; IC9.22 3775,6.49 4025,6.49 v1(4075,56.49) ; v1(4925,6.49) IC10.22
NetIC6_37: IC6.37 QG1.8 | length 1120.7
  Bottom w12: QG1.8 600,481.49 625,456.49 625,-118.51 650,-143.51 IC6.37
NetIC6_38: IC6.38 R7.1 | length 175
  Bottom w12: IC6.38 R7.1
NetIC9_2: IC9.2
NetIC9_3: IC9.3
NetIC9_4: IC9.4
NetIC9_5: IC9.5
NetIC9_6: IC9.6
NetIC9_7: IC9.7
NetIC9_8: IC9.8
NetIC9_9: IC9.9 R10.2 | length 1200
  Top w12: v1(4025,-1343.51) v1(4025,-993.51)
  Bottom w12: R10.2 v1(4025,-1343.51) ; v1(4025,-993.51) IC9.9
NetIC9_14: IC9.14 | length 695.7
  Bottom w12: IC9.14 4900,-493.51 4950,-543.51
NetIC9_15: IC9.15 | length 695.7
  Bottom w12: IC9.15 4900,-393.51 4950,-443.51
NetIC9_16: IC9.16
NetIC9_17: IC9.17
NetIC11_6: IC11.6 Q1.1 | length 289.4
  Bottom w16: IC11.6 4430,931.49 Q1.1
NetIC11_10: IC11.10 JP4.2 | length 1393.2
  Bottom w12: JP4.2 3175,1556.49 3350,1381.49 4075,1381.49 4125,1331.49 IC11.10
NetIC11_12: IC11.12 JP4.3 | length 1237.1
  Bottom w12: JP4.3 3275,1581.49 3375,1481.49 3975,1481.49 4025,1531.49 IC11.12
NetLED1_A: LED1.A R10.1 | length 100
  Bottom w12: LED1.A R10.1
NetLED2_A: LED2.A R11.1 | length 230.4
  Bottom w16: R11.1 685,1290 710,1315 LED2.A
VCC: C1.2 C2.2 C5.2 C6.2 C8.2 C9.2 C10.2 C11.2 C12.2 C13.2 C14.2 IC1.4 IC1.8 IC2.14 IC3.14 IC4.14 IC5.6 IC5.16 IC6.8 IC7.27 IC7.28 IC8.28 IC9.20 IC9.24 IC10.20 IC10.24 IC11.2 IC11.15 J1.3 JP1.1 PS2.2 PS2.18 PS2.20 QG1.14 R1.2 R2.2 R3.2 R4.2 R5.2 R6.2 R7.2 R11.2 VGA.2 VGA.20 | length 28762.4
  Top w16: v1(650,-1768.51) v1(650,-543.51) ; v1(1650,581.49) v1(1650,1181.49) v1(1650,1756.49) ; v1(1725,-1643.51) v1(1725,-1743.51) 1725,-1818.51 2470,-1818.51 ; C6.2 2470,-1818.51 ; v1(2750,-1868.51) 2750,-1818.51 ; v1(2750,-1743.51) 2750,-1818.51 ; v1(4175,531.49) v1(4175,1881.49) ; v1(4425,531.49) v1(4675,531.49) ; v1(4975,-1843.51) v1(4975,-1443.51) v1(4975,-193.51) ; IC10.20@5671.49,110 IC10.20 ; 2470,-1818.51 2750,-1818.51
  Bottom w12: 275,-843.51 300,-818.51 300,-593.51 325,-543.51 IC6.8@375,-543.51 ; 875,531.49 1050,531.49 R2.2 1175,406.49 R7.2 ; 1625,581.49 v1(1650,581.49) ; 1625,1181.49 v1(1650,1181.49) ; v1(1650,1756.49) 1650,1781.49
  Bottom w16: C5.2 R6.2 125,-968.51 125,-843.51 ; R5.2 125,-93.51 ; 275,-843.51 125,-843.51 ; IC6.8@375,-543.51 IC6.8 v1(650,-543.51) ; v1(650,-1768.51) 700,-1818.51 1075,-1818.51 1150,-1743.51 IC7.28 v1(1725,-1743.51) ; R11.2 575,1525 ; R3.2 700,481.49 ; C2.2 700,481.49 ; R1.2 1000,1031.49 IC1.8 900,931.49 875,906.49 875,531.49 700,531.49 ; IC7.27 v1(1725,-1643.51) ; C11.2 1600,556.49 1625,581.49 ; C1.2 1600,1156.49 1625,1181.49 ; C10.2 1600,1756.49 ; v1(1650,581.49) IC4.14 ; v1(1650,1181.49) IC3.14 ; v1(1650,1756.49) 1600,1756.49 ; IC2.14 1650,1781.49 1650,1856.49 1675,1881.49 2975,1881.49 ; v1(2750,-1868.51) C9.2 ; v1(2750,-1743.51) IC8.28 ; IC5.6 2950,831.49 2975,856.49 2975,956.49 2950,981.49 2825,981.49 2800,1006.49 2800,1381.49 2825,1406.49 2975,1406.49 ; IC5.16 3175,1406.49 2975,1406.49 ; IC9.24 4100,-193.51 4125,-168.51 4125,106.49 ; IC11.15 C8.2 3500,1881.49 ; v1(4175,1881.49) 3500,1881.49 ; C13.2 4375,131.49 4350,106.49 IC9.20 4125,106.49 ; v1(4425,531.49) IC11.2 v1(4175,531.49) 4175,231.49 4125,181.49 4125,106.49 ; v1(4675,531.49) 4675,256.49 4750,181.49 4875,181.49 ; v1(4975,-1843.51) 6010,-1843.51 VGA.20 ; IC10.24 v1(4975,-193.51) 4875,-93.51 4875,181.49 ; VGA.2 6010,105 ; PS2.2 6112.6,1237.4 6115,1235 6115,440 6112.4,437.4 PS2.18 PS2.20 6010,105 ; 125,-843.51 125,-668.51 75,-618.51 75,-493.51 125,-443.51 125,-93.51 ; 125,-93.51 125,250 156.49,281.49 R4.2 300,281.49 325,306.49 325,606.49 350,631.49 475,631.49 ; 475,631.49 IC1.4 700,531.49 ; 475,631.49 QG1.14 425,1131.49 J1.3 556.89,1413.39 575,1431.49 575,1525 ; 575,1525 575,1750 610,1785 JP1.1 881.49,1785 910,1756.49 1600,1756.49 ; 700,481.49 700,531.49 ; 2975,1406.49 C12.2 2975,1881.49 ; 2975,1881.49 3500,1881.49 ; 4875,181.49 5503.51,181.49 5580,105 5673.51,105 IC10.20 6008.51,106.49 6010,105
VIA1_PB0: IC9.10 PS2.4 | length 4858.2
  Top w12: 4175,-1893.51 v1(4175,-893.51) ; v1(5125,-945) 5150,-920 5150,1025 5215,1090 5962.6,1090 PS2.4
  Bottom w12: v1(4175,-893.51) IC9.10 4873.51,-893.51 4925,-945 v1(5125,-945)
VIA1_PB1: IC9.11 PS2.5 | length 3478.7
  Top w12: v1(5185,-845) 5210,-820 5210,960 5285,1035 5907.6,1035 PS2.5
  Bottom w12: IC9.11 4900,-793.51 4951.49,-845 v1(5185,-845)
VIA1_PB2: IC9.12 VGA.13 | length 1787.2
  Top w12: v1(5745,-750) 5750,-755 5815,-755 5845,-785 5845,-872.4 VGA.13
  Bottom w12: IC9.12 4900,-693.51 4950,-743.51 5738.51,-743.51 v1(5745,-750)
VIA1_PB3: IC9.13 VGA.18 | length 2375.8
  Bottom w12: IC9.13 4900,-593.51 4950,-643.51 5818.51,-643.51 5865,-690 6060,-690 6105,-735 6105,-1120 6087.6,-1137.4 VGA.18
VIA2_PA0: IC10.2 VGA.16 | length 923.1
  Bottom w12: IC10.2 5891.49,-1693.51 5960,-1625 5960,-1085 6007.6,-1037.4 VGA.16
VIA2_PA1: IC10.3 VGA.15 | length 712.9
  Bottom w12: IC10.3 5776.49,-1593.51 5855,-1515 5855,-1092.4 VGA.15
VIA2_PA2: IC10.4 VGA.12 | length 910
  Bottom w12: IC10.4 5776.49,-1493.51 5815,-1455 5815,-1020 5850,-985 5945,-985 5960,-970 5960,-887.4 VGA.12
VIA2_PA3: IC10.5 VGA.9 | length 852.4
  Bottom w12: IC10.5 5746.49,-1393.51 5785,-1355 5785,-765 5812.6,-737.4 VGA.9
VIA2_PA4: IC10.6 VGA.10 | length 1018.2
  Top w12: IC10.6 6066.49,-1293.51 6090,-1270 6090,-770 6057.4,-737.4 VGA.10
VIA2_PA5: IC10.7 VGA.8 | length 1553.1
  Top w12: IC10.7 5601.49,-1193.51 5580,-1215 5580,-1335 5590,-1345 6080,-1345 6125,-1300 6125,-665 6100,-640 6012.6,-640 VGA.8
VIA2_PA6: IC10.8 VGA.5 | length 2999.6
  Top w12: IC10.8 5751.49,-1093.51 5785,-1060 5785,-965 5765,-945 5575,-945 5515,-1005 5515,-1500 5560,-1545 6145,-1545 6185,-1505 6185,-545 6130,-490 5957.4,-490 VGA.5
VIA2_PA7: IC10.9 VGA.6 | length 2135
  Top w12: IC10.9 5581.49,-993.51 5550,-1025 5550,-1410 5585,-1445 6100,-1445 6155,-1390 6155,-585 6110,-540 6012.6,-540 VGA.6
VIA2_PB0: IC10.10 PS2.7 | length 2666.4
  Top w12: IC10.10 5593.51,-893.51 5250,-550 5250,855 5332.4,937.4 PS2.7
VIA2_PB1: IC10.11 PS2.9 | length 2445.7
  Top w12: v2@5432.5,837.5 5347.5,837.5 5290,780 5290,-520 5563.51,-793.51 IC10.11
  Bottom w12: v2(5430,840) 5432.6,837.4 PS2.9
VIA2_PB2: IC10.12 PS2.11 | length 2181.5
  Top w12: v2@5412.5,737.5 5367.5,737.5 5325,695 5325,-415 5603.51,-693.51 IC10.12
  Bottom w12: v2(5410,740) 5412.6,737.4 PS2.11
VIA2_PB3: IC10.13 PS2.13 | length 1935.2
  Top w12: v1(5395,640) 5365,610 5365,-360 5598.51,-593.51 IC10.13
  Bottom w12: v1(5395,640) 5397.6,637.4 PS2.13
VIA2_PB4: IC10.14 PS2.8 | length 1964.7
  Top w12: IC10.14 5603.51,-493.51 5445,-335 5445,650 5685,890 5962.6,890 PS2.8
VIA2_PB5: IC10.15 PS2.10 | length 1756.7
  Top w12: IC10.15 5598.51,-393.51 5490,-285 5490,640 5640,790 5962.6,790 PS2.10
VIA2_PB6: IC10.16 PS2.12 | length 1548.7
  Top w12: IC10.16 5598.51,-293.51 5535,-230 5535,635 5585,685 5957.6,685 PS2.12
VIA2_PB7: IC10.17 PS2.14 | length 1276.3
  Top w12: IC10.17 5608.51,-193.51 5580,-165 5580,530 5635,585 5957.6,585 PS2.14
pads on no net: IC1.5 IC2.8 IC2.9 IC2.10 IC2.11 IC2.12 IC2.13 IC3.5 IC3.6 IC3.8 IC3.9 IC3.12 IC3.13 IC4.9 IC4.10 IC4.13 IC5.7 IC5.9 IC5.10 IC5.11 IC5.12 IC6.3 IC6.5 IC6.7 IC6.35 IC6.36 IC9.18 IC9.19 IC9.39 IC9.40 IC10.18 IC10.19 IC10.39 IC10.40 IC11.5 IC11.8 IC11.11 PS2.3 PS2.6 PS2.16 RESET.1 RESET.3 VGA.3 VGA.4 VGA.7 VGA.11 VGA.14

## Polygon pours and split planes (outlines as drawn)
GND on Top "GND_L01_P002" (solid, remove dead copper, pour order 2): 0,-1968.51 6299.21,-1968.51 6299.21,1968.51 0,1968.51
GND on Bottom "GND_L02_P004" (solid, remove dead copper, pour order 4): 0,-1968.51 6299.21,-1968.51 6299.21,1968.51 0,1968.51

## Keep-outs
Keep-Out Layer:
  lines w0: 0,1968.51 0,-1968.51 6299.21,-1968.51 6299.21,1968.51

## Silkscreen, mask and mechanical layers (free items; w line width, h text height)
Top Overlay:
  text "VCC" at 795,1760 h78.74
  text "GND" at 800,1665 h78.74
  text "G" at 3055,1640 h78.74
  text "T" at 3160,1640 h78.74
  text "R" at 3255,1640 h78.74
  text "HC6502 by" at 4690,1485 h108.5
  text "Inspired by Dirk Grappendorf" at 4815,1290 h59.06
  text "HC6502" at 2290,-95 h393.7
Dimension:
  the board outline again, w0

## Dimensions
0,-1968.51 to 6299.21,-1968.51 on Top Overlay
0,1968.51 to 0,-1968.51 on Top Overlay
